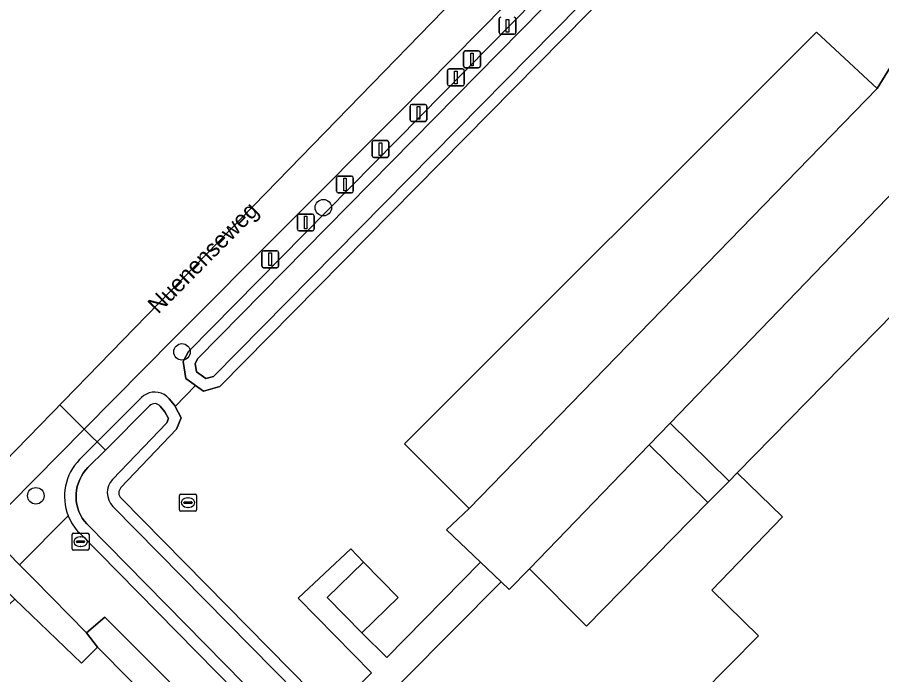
# Model space of a CAD drawing. Extents: x 162788 to 163838, y 385791 to 386523.
# Drawn here: x 162932.6 to 162983.7, y 386211.9 to 386250.8 of the extents above; entities that cross this region are included whole.
import ezdxf

# ---------------------------------------------------------------- set-up
doc = ezdxf.new("R2010")
doc.units = 0
for name, color, linetype in [('IMGEO_Afsluitpaal', 7, 'Continuous'), ('IMGEO_Boom', 7, 'Continuous'), ('IMGEO_Brandkraan', 7, 'Continuous'), ('IMGEO_Duiker', 7, 'Continuous'), ('IMGEO_Erf', 7, 'Continuous'), ('IMGEO_Groenvoorziening', 7, 'Continuous'), ('IMGEO_Oever', 7, 'Continuous'), ('IMGEO_Openbare_ruimte_label', 7, 'Continuous'), ('IMGEO_Pand', 7, 'Continuous'), ('IMGEO_Parkeervlak_halfverhard', 7, 'Continuous'), ('IMGEO_Rijbaan_lokaal_open', 7, 'Continuous'), ('IMGEO_Rioolput', 7, 'Continuous'), ('IMGEO_Voetpad_gesloten', 7, 'Continuous'), ('IMGEO_Voetpad_open', 7, 'Continuous'), ('IMGEO_Waterloop', 7, 'Continuous'), ('IMGEO_Woonerf_open', 7, 'Continuous')]:
    doc.layers.add(name, color=color, linetype=linetype)

msp = doc.modelspace()

# ---------------------------------------------------------------- linework, layer by layer
at = {"layer": 'IMGEO_Afsluitpaal'}
for p, q in [((162961.092, 386249.9), (162961.092, 386250.7)), ((162961.092, 386250.7), (162961.092, 386249.9)), ((162962.082, 386250.7), (162962.082, 386249.9)), ((162962.082, 386249.9), (162962.082, 386250.7)), ((162961.982, 386249.8), (162961.192, 386249.8)), ((162961.192, 386249.8), (162961.982, 386249.8)), ((162958.991, 386247.91), (162958.991, 386248.71)), ((162958.991, 386248.71), (162958.991, 386247.91)), ((162959.091, 386248.81), (162959.881, 386248.81)), ((162959.881, 386248.81), (162959.091, 386248.81)), ((162959.981, 386248.71), (162959.981, 386247.91)), ((162959.981, 386247.91), (162959.981, 386248.71)), ((162958.033, 386246.841), (162958.033, 386247.641)), ((162958.033, 386247.641), (162958.033, 386246.841)), ((162958.133, 386247.741), (162958.923, 386247.741)), ((162958.923, 386247.741), (162958.133, 386247.741)), ((162959.023, 386247.641), (162959.023, 386246.841)), ((162959.023, 386246.841), (162959.023, 386247.641)), ((162959.881, 386247.81), (162959.091, 386247.81)), ((162959.091, 386247.81), (162959.881, 386247.81)), ((162958.923, 386246.741), (162958.133, 386246.741)), ((162958.133, 386246.741), (162958.923, 386246.741)), ((162955.822, 386244.74), (162955.822, 386245.54)), ((162955.822, 386245.54), (162955.822, 386244.74)), ((162955.922, 386245.64), (162956.712, 386245.64)), ((162956.712, 386245.64), (162955.922, 386245.64)), ((162956.812, 386245.54), (162956.812, 386244.74)), ((162956.812, 386244.74), (162956.812, 386245.54)), ((162956.712, 386244.64), (162955.922, 386244.64)), ((162955.922, 386244.64), (162956.712, 386244.64)), ((162953.574, 386242.603), (162953.574, 386243.403)), ((162953.574, 386243.403), (162953.574, 386242.603)), ((162953.674, 386243.503), (162954.464, 386243.503)), ((162954.464, 386243.503), (162953.674, 386243.503)), ((162954.564, 386243.403), (162954.564, 386242.603)), ((162954.564, 386242.603), (162954.564, 386243.403)), ((162954.464, 386242.503), (162953.674, 386242.503)), ((162953.674, 386242.503), (162954.464, 386242.503)), ((162951.473, 386240.502), (162951.473, 386241.302)), ((162951.473, 386241.302), (162951.473, 386240.502)), ((162951.573, 386241.402), (162952.363, 386241.402)), ((162952.363, 386241.402), (162951.573, 386241.402)), ((162952.463, 386241.302), (162952.463, 386240.502)), ((162952.463, 386240.502), (162952.463, 386241.302)), ((162952.363, 386240.402), (162951.573, 386240.402)), ((162951.573, 386240.402), (162952.363, 386240.402)), ((162949.151, 386238.254), (162949.151, 386239.054)), ((162949.151, 386239.054), (162949.151, 386238.254)), ((162949.251, 386239.154), (162950.041, 386239.154)), ((162950.041, 386239.154), (162949.251, 386239.154)), ((162950.141, 386239.054), (162950.141, 386238.254)), ((162950.141, 386238.254), (162950.141, 386239.054)), ((162950.041, 386238.154), (162949.251, 386238.154)), ((162949.251, 386238.154), (162950.041, 386238.154)), ((162947.05, 386236.079), (162947.05, 386236.879)), ((162947.05, 386236.879), (162947.05, 386236.079)), ((162947.15, 386236.979), (162947.94, 386236.979)), ((162947.94, 386236.979), (162947.15, 386236.979)), ((162948.04, 386236.879), (162948.04, 386236.079)), ((162948.04, 386236.079), (162948.04, 386236.879)), ((162947.94, 386235.979), (162947.15, 386235.979)), ((162947.15, 386235.979), (162947.94, 386235.979))]:
    msp.add_line(p, q, dxfattribs=at)
for points in [[(162961.512, 386250.675), (162961.662, 386250.675), (162961.662, 386249.925), (162961.512, 386249.925), (162961.512, 386250.675)], [(162959.411, 386248.685), (162959.561, 386248.685), (162959.561, 386247.935), (162959.411, 386247.935), (162959.411, 386248.685)], [(162958.453, 386247.616), (162958.603, 386247.616), (162958.603, 386246.866), (162958.453, 386246.866), (162958.453, 386247.616)], [(162956.242, 386245.515), (162956.392, 386245.515), (162956.392, 386244.765), (162956.242, 386244.765), (162956.242, 386245.515)], [(162953.994, 386243.378), (162954.144, 386243.378), (162954.144, 386242.628), (162953.994, 386242.628), (162953.994, 386243.378)], [(162951.893, 386241.277), (162952.043, 386241.277), (162952.043, 386240.527), (162951.893, 386240.527), (162951.893, 386241.277)], [(162949.571, 386239.029), (162949.721, 386239.029), (162949.721, 386238.279), (162949.571, 386238.279), (162949.571, 386239.029)], [(162947.47, 386236.854), (162947.62, 386236.854), (162947.62, 386236.104), (162947.47, 386236.104), (162947.47, 386236.854)]]:
    msp.add_lwpolyline(points, dxfattribs=at)
for centre, start, end in [((162961.192, 386250.7), 90, 180), ((162961.192, 386250.7), 90, 180), ((162961.982, 386250.7), 0, 90), ((162961.982, 386250.7), 360, 90), ((162961.192, 386249.9), 180, 270), ((162961.192, 386249.9), 180, 270), ((162961.982, 386249.9), 270, 0), ((162961.982, 386249.9), 270, 0), ((162959.091, 386248.71), 90, 180), ((162959.091, 386248.71), 90, 180), ((162959.881, 386248.71), 0, 90), ((162959.881, 386248.71), 360, 90), ((162959.091, 386247.91), 180, 270), ((162959.091, 386247.91), 180, 270), ((162959.881, 386247.91), 270, 0), ((162959.881, 386247.91), 270, 0), ((162958.133, 386247.641), 90, 180), ((162958.133, 386247.641), 90, 180), ((162958.923, 386247.641), 0, 90), ((162958.923, 386247.641), 360, 90), ((162958.133, 386246.841), 180, 270), ((162958.133, 386246.841), 180, 270), ((162958.923, 386246.841), 270, 0), ((162958.923, 386246.841), 270, 0), ((162955.922, 386245.54), 90, 180), ((162955.922, 386245.54), 90, 180), ((162956.712, 386245.54), 0, 90), ((162956.712, 386245.54), 360, 90), ((162955.922, 386244.74), 180, 270), ((162955.922, 386244.74), 180, 270), ((162956.712, 386244.74), 270, 0), ((162956.712, 386244.74), 270, 0), ((162953.674, 386243.403), 90, 180), ((162953.674, 386243.403), 90, 180), ((162954.464, 386243.403), 0, 90), ((162954.464, 386243.403), 360, 90), ((162953.674, 386242.603), 180, 270), ((162953.674, 386242.603), 180, 270), ((162954.464, 386242.603), 270, 0), ((162954.464, 386242.603), 270, 0), ((162951.573, 386241.302), 90, 180), ((162951.573, 386241.302), 90, 180), ((162952.363, 386241.302), 0, 90), ((162952.363, 386241.302), 360, 90), ((162951.573, 386240.502), 180, 270), ((162951.573, 386240.502), 180, 270), ((162952.363, 386240.502), 270, 0), ((162952.363, 386240.502), 270, 0), ((162949.251, 386239.054), 90, 180), ((162949.251, 386239.054), 90, 180), ((162950.041, 386239.054), 0, 90), ((162950.041, 386239.054), 360, 90), ((162949.251, 386238.254), 180, 270), ((162949.251, 386238.254), 180, 270), ((162950.041, 386238.254), 270, 0), ((162950.041, 386238.254), 270, 0), ((162947.15, 386236.879), 90, 180), ((162947.15, 386236.879), 90, 180), ((162947.94, 386236.879), 0, 90), ((162947.94, 386236.879), 360, 90), ((162947.15, 386236.079), 180, 270), ((162947.15, 386236.079), 180, 270), ((162947.94, 386236.079), 270, 0), ((162947.94, 386236.079), 270, 0)]:
    msp.add_arc(centre, 0.1, start, end, dxfattribs=at)
at = {"layer": 'IMGEO_Boom'}
for centre in [(162950.69, 386239.534), (162942.324, 386230.997), (162933.674, 386222.48)]:
    msp.add_circle(centre, 0.489, dxfattribs=at)
at = {"layer": 'IMGEO_Brandkraan'}
for p, q in [((162935.821, 386219.335), (162935.821, 386220.187)), ((162935.896, 386220.261), (162936.748, 386220.261)), ((162936.123, 386219.804), (162936.521, 386219.804)), ((162936.309, 386220.041), (162936.334, 386220.041)), ((162936.822, 386220.187), (162936.822, 386219.335)), ((162936.748, 386219.261), (162935.896, 386219.261)), ((162936.08, 386219.755), (162936.08, 386219.767)), ((162936.518, 386219.718), (162936.12, 386219.718)), ((162936.332, 386219.481), (162936.307, 386219.481)), ((162936.564, 386219.767), (162936.564, 386219.755))]:
    msp.add_line(p, q, dxfattribs=at)
for points in [[(162935.821, 386219.335), (162935.821, 386220.187)], [(162935.896, 386220.261), (162936.748, 386220.261)], [(162936.822, 386220.187), (162936.822, 386219.335)], [(162936.748, 386219.261), (162935.896, 386219.261)]]:
    msp.add_lwpolyline(points, dxfattribs=at)
for centre, radius, start, end in [((162935.898, 386220.185), 0.0765, 91.552, 178.448), ((162935.898, 386220.185), 0.0765, 91.552, 178.448), ((162936.12, 386219.764), 0.0403, 85.8775, 175.7526), ((162936.525, 386219.766), 0.0386, 1.7309, 96.639), ((162936.746, 386220.185), 0.0765, 1.552, 88.448), ((162936.746, 386220.185), 0.0765, 1.552, 88.448), ((162935.898, 386219.337), 0.0765, 181.552, 268.448), ((162935.898, 386219.337), 0.0765, 181.552, 268.448), ((162936.117, 386219.754), 0.0366, 178.938, 274.7102), ((162936.521, 386219.761), 0.043, 264.8664, 352.4533), ((162936.746, 386219.337), 0.0765, 271.552, 358.448), ((162936.746, 386219.337), 0.0765, 271.552, 358.448)]:
    msp.add_arc(centre, radius, start, end, dxfattribs=at)
for centre, major_axis, ratio, start_param, end_param in [((162936.308, 386219.761), (-0.387, 0.002), 0.722429, 4.712389, 7.853982), ((162936.333, 386219.761), (-0.39, 0.002), 0.717154, 1.570796, 4.712389)]:
    msp.add_ellipse(centre, major_axis=major_axis, ratio=ratio, start_param=start_param, end_param=end_param, dxfattribs=at)
at = {"layer": 'IMGEO_Duiker'}
msp.add_lwpolyline([(162935.089, 386227.868), (162935.089, 386227.868), (162936.539, 386226.429), (162937.792, 386225.185)], dxfattribs=at)
at = {"layer": 'IMGEO_Erf'}
for points in [[(163019.415, 386221.829), (163017.215, 386224.903), (163006.507, 386217.247), (163004.811, 386216.063), (162998.839, 386211.871), (163000, 386210.448), (163000.138, 386210.278), (162990.677, 386200.741), (162991.908, 386199.494), (162983.103, 386190.616), (162967.863, 386205.517), (162976.444, 386214.191), (162973.671, 386216.902), (162977.86, 386221.232), (162975.179, 386223.844)], [(162975.179, 386223.844), (162974.697, 386223.353), (162973.449, 386222.082), (162966.269, 386214.768), (162962.884, 386218.155), (162961.686, 386216.939), (162961.22, 386217.38), (162952.648, 386208.766), (162952.362, 386208.479), (162969.976, 386190.594), (162979.54, 386180.693), (162978.922, 386179.765), (162983.538, 386182.642), (162989.546, 386186.246), (163000.557, 386193.158), (163003.461, 386197.095), (163012.04, 386206.871), (163017.413, 386210.52), (163018.585, 386211.639), (163019.242, 386212.566)], [(162970.367, 386180.135), (162937.328, 386213.523), (162936.374, 386212.581), (162932.44, 386216.361), (162931.108, 386215.134), (162928.515, 386213.329), (162923.893, 386210.577)]]:
    msp.add_lwpolyline(points, dxfattribs=at)
at = {"layer": 'IMGEO_Groenvoorziening'}
for points in [[(163024.046, 386310.479), (163023.535, 386310.538), (163023.359, 386310.538), (163020.272, 386307.421), (163020.444, 386307.251), (163020.549, 386306.986), (163020.601, 386306.514), (163020.576, 386306.01), (163000.486, 386285.642), (162964.856, 386249.521), (162944.555, 386228.94), (162943.594, 386228.666), (162943.128, 386229.005), (162941.921, 386227.771), (162942.281, 386227.087), (162942.005, 386226.417), (162938.714, 386222.971)], [(163020.041, 386309.917), (163018.251, 386309.139), (163000, 386290.614), (162987.698, 386278.128), (162959.944, 386250), (162955.09, 386245.08), (162941.853, 386231.809), (162936.539, 386226.429), (162930.665, 386220.482), (162932.714, 386218.395), (162935.593, 386221.295)], [(162941.557, 386228.226), (162941.883, 386227.843), (162941.921, 386227.771), (162943.128, 386229.005), (162943.049, 386229.062), (162942.55, 386229.422), (162942.399, 386230.424), (162942.706, 386231.014), (162961.879, 386250.479), (162999.514, 386288.687)], [(162938.719, 386222.331), (162951.211, 386209.647), (162952.362, 386208.479), (162952.648, 386208.766), (162951.461, 386209.9), (162953.535, 386211.999), (162949.195, 386216.429), (162952.316, 386219.349), (162953.056, 386218.558), (162955.114, 386216.454), (162952.973, 386214.359), (162954.437, 386212.913), (162959.997, 386218.541), (162957.977, 386220.457), (162959.309, 386221.733), (162955.489, 386225.556), (162979.879, 386249.927), (162983.465, 386246.582), (162984.886, 386248.887), (162987.744, 386256.107), (162989.775, 386258.919), (162997.171, 386269.163)], [(162936.266, 386224.619), (162937.308, 386225.666), (162939.922, 386228.29)], [(162935.593, 386221.295), (162932.714, 386218.395), (162933.575, 386217.518), (162936.664, 386214.373), (162937.755, 386215.292), (162947.333, 386205.72), (162948.52, 386206.922), (162949.688, 386205.791), (162950.095, 386206.2), (162948.953, 386207.361), (162936.252, 386220.279)]]:
    msp.add_lwpolyline(points, dxfattribs=at)
for centre, radius, start, end in [((162940.712, 386227.489), 1.125, 60.8142, 134.5938), ((162940.691, 386227.479), 1.143, 40.7862, 60.1742), ((162938.474, 386222.442), 3.101, 135.4068, 201.7016), ((162939.047, 386222.654), 0.46, 136.3947, 224.5005), ((162938.483, 386222.448), 3.111, 201.7464, 224.1902)]:
    msp.add_arc(centre, radius, start, end, dxfattribs=at)
at = {"layer": 'IMGEO_Oever'}
for points in [[(163020.549, 386306.986), (163020.444, 386307.251), (163020.272, 386307.421), (163019.984, 386307.707), (163019.635, 386307.884), (163019.077, 386308.032), (163018.618, 386308.083), (162999.514, 386288.687), (162961.879, 386250.479), (162942.706, 386231.014), (162942.399, 386230.424), (162942.55, 386229.422), (162943.049, 386229.062), (162943.128, 386229.005), (162943.594, 386228.666), (162944.555, 386228.94), (162964.856, 386249.521), (163000.486, 386285.642), (163020.576, 386306.01), (163020.601, 386306.514)], [(163019.628, 386306.02), (163000, 386286.121), (162964.37, 386250), (162944.195, 386229.547), (162943.726, 386229.413), (162943.449, 386229.614), (162943.182, 386229.807), (162943.107, 386230.306), (162943.264, 386230.608), (162962.365, 386250), (163000, 386288.208), (163018.608, 386307.1), (163019.184, 386306.49)]]:
    msp.add_lwpolyline(points, close=True, dxfattribs=at)
for points in [[(162939.922, 386228.29), (162937.308, 386225.666), (162936.266, 386224.619)], [(162938.714, 386222.971), (162942.005, 386226.417), (162942.281, 386227.087), (162941.921, 386227.771), (162941.883, 386227.843), (162941.557, 386228.226)], [(162977.188, 386179.619), (162936.744, 386220.751), (162936.686, 386220.813), (162936.548, 386220.979), (162936.425, 386221.157), (162936.318, 386221.346), (162936.229, 386221.543), (162936.158, 386221.747), (162936.105, 386221.957), (162936.071, 386222.171), (162936.057, 386222.387), (162936.061, 386222.603), (162936.086, 386222.818), (162936.129, 386223.03), (162936.191, 386223.238), (162936.271, 386223.439), (162936.369, 386223.632), (162936.484, 386223.815), (162936.614, 386223.988), (162936.76, 386224.148), (162937.792, 386225.185), (162940.405, 386227.808)], [(162941.038, 386227.783), (162941.315, 386227.458), (162941.529, 386227.052), (162941.423, 386226.795), (162938.221, 386223.442)], [(162952.362, 386208.479), (162951.211, 386209.647), (162938.719, 386222.331)], [(162938.232, 386221.853), (162969.488, 386190.118)], [(162936.252, 386220.279), (162948.953, 386207.361), (162950.095, 386206.2), (162976.888, 386178.951), (162977.561, 386178.917), (162978.922, 386179.765), (162979.54, 386180.693), (162969.976, 386190.594), (162952.362, 386208.479)]]:
    msp.add_lwpolyline(points, dxfattribs=at)
for centre, radius, start, end in [((162940.712, 386227.489), 1.125, 60.8142, 134.5938), ((162940.691, 386227.479), 1.143, 40.7862, 60.1742), ((162940.71, 386227.503), 0.431, 40.4697, 135.0069), ((162938.474, 386222.442), 3.101, 135.4068, 201.7016), ((162939.047, 386222.653), 1.142, 136.3343, 224.459), ((162939.047, 386222.654), 0.46, 136.3947, 224.5005), ((162938.483, 386222.448), 3.111, 201.7464, 224.1902)]:
    msp.add_arc(centre, radius, start, end, dxfattribs=at)
at = {"layer": 'IMGEO_Pand'}
for points in [[(163004.708, 386220.778), (163012.988, 386226.739), (163001.488, 386242.784), (162990.889, 386235.198), (162988.569, 386237.483), (162975.179, 386223.844), (162977.86, 386221.232), (162973.671, 386216.902), (162976.444, 386214.191), (162967.863, 386205.517), (162983.103, 386190.616), (162991.908, 386199.494), (162990.677, 386200.741), (163000.138, 386210.278), (163000, 386210.448), (162998.839, 386211.871), (163004.811, 386216.063), (163002.528, 386219.208), (163004.161, 386220.384)], [(162955.114, 386216.454), (162953.056, 386218.558), (162950.915, 386216.463), (162952.973, 386214.359)]]:
    msp.add_lwpolyline(points, close=True, dxfattribs=at)
at = {"layer": 'IMGEO_Parkeervlak_halfverhard'}
for points in [[(162983.465, 386246.582), (162979.879, 386249.927), (162955.489, 386225.556), (162959.309, 386221.733)], [(162988.569, 386237.483), (162995.78, 386244.695), (162992.066, 386248.409), (162971.204, 386226.781), (162974.697, 386223.353), (162975.179, 386223.844)], [(162973.449, 386222.082), (162969.968, 386225.5), (162962.884, 386218.155), (162966.269, 386214.768)]]:
    msp.add_lwpolyline(points, close=True, dxfattribs=at)
at = {"layer": 'IMGEO_Rijbaan_lokaal_open'}
msp.add_lwpolyline([(163145.974, 386442.657), (162994.999, 386289.478), (162926.188, 386218.715), (162917.231, 386215.618), (162918.642, 386212.196), (162921.179, 386213.365), (162927.186, 386216.882), (162929.139, 386218.937), (162929.526, 386219.329), (162930.665, 386220.482), (162936.539, 386226.429), (162941.853, 386231.809), (162955.09, 386245.08), (162959.944, 386250), (162987.698, 386278.128), (163000, 386290.614), (163018.251, 386309.139), (163024.508, 386315.489), (163032.796, 386323.924)], dxfattribs=at)
at = {"layer": 'IMGEO_Rioolput'}
for p, q in [((162942.177, 386221.649), (162942.177, 386222.501)), ((162942.252, 386222.575), (162943.104, 386222.575)), ((162942.665, 386222.355), (162942.69, 386222.355)), ((162943.178, 386222.501), (162943.178, 386221.649)), ((162942.436, 386222.069), (162942.436, 386222.081)), ((162942.874, 386222.032), (162942.476, 386222.032)), ((162942.479, 386222.118), (162942.877, 386222.118)), ((162942.92, 386222.081), (162942.92, 386222.069)), ((162943.104, 386221.575), (162942.252, 386221.575)), ((162942.688, 386221.795), (162942.663, 386221.795))]:
    msp.add_line(p, q, dxfattribs=at)
for points in [[(162942.177, 386221.649), (162942.177, 386222.501)], [(162942.252, 386222.575), (162943.104, 386222.575)], [(162943.178, 386222.501), (162943.178, 386221.649)], [(162943.104, 386221.575), (162942.252, 386221.575)]]:
    msp.add_lwpolyline(points, dxfattribs=at)
for centre, radius, start, end in [((162942.254, 386222.499), 0.0765, 91.552, 178.448), ((162942.254, 386222.499), 0.0765, 91.552, 178.448), ((162943.102, 386222.499), 0.0765, 1.552, 88.448), ((162943.102, 386222.499), 0.0765, 1.552, 88.448), ((162942.476, 386222.078), 0.0403, 85.8775, 175.7526), ((162942.473, 386222.068), 0.0366, 178.938, 274.7102), ((162942.877, 386222.075), 0.043, 264.8664, 352.4533), ((162942.881, 386222.08), 0.0386, 1.7309, 96.639), ((162942.254, 386221.651), 0.0765, 181.552, 268.448), ((162942.254, 386221.651), 0.0765, 181.552, 268.448), ((162943.102, 386221.651), 0.0765, 271.552, 358.448), ((162943.102, 386221.651), 0.0765, 271.552, 358.448)]:
    msp.add_arc(centre, radius, start, end, dxfattribs=at)
for centre, major_axis, ratio, start_param, end_param in [((162942.664, 386222.075), (-0.387, 0.002), 0.722429, 4.712389, 7.853982), ((162942.689, 386222.075), (-0.39, 0.002), 0.717154, 1.570796, 4.712389)]:
    msp.add_ellipse(centre, major_axis=major_axis, ratio=ratio, start_param=start_param, end_param=end_param, dxfattribs=at)
at = {"layer": 'IMGEO_Voetpad_gesloten'}
msp.add_lwpolyline([(162933.575, 386217.518), (162932.714, 386218.395), (162930.665, 386220.482), (162929.526, 386219.329), (162931.15, 386217.665), (162932.44, 386216.361), (162936.374, 386212.581), (162937.328, 386213.523), (162936.664, 386214.373)], close=True, dxfattribs=at)
at = {"layer": 'IMGEO_Voetpad_open'}
for points in [[(162974.697, 386223.353), (162971.204, 386226.781), (162969.968, 386225.5), (162973.449, 386222.082)], [(162961.22, 386217.38), (162959.997, 386218.541), (162954.437, 386212.913), (162952.973, 386214.359), (162950.915, 386216.463), (162953.056, 386218.558), (162952.316, 386219.349), (162949.195, 386216.429), (162953.535, 386211.999), (162951.461, 386209.9), (162952.648, 386208.766)]]:
    msp.add_lwpolyline(points, close=True, dxfattribs=at)
at = {"layer": 'IMGEO_Waterloop'}
msp.add_lwpolyline([(162943.449, 386229.614), (162943.726, 386229.413), (162944.195, 386229.547), (162964.37, 386250), (163000, 386286.121), (163019.628, 386306.02), (163019.184, 386306.49), (163018.608, 386307.1), (163000, 386288.208), (162962.365, 386250), (162943.264, 386230.608), (162943.107, 386230.306), (162943.182, 386229.807)], close=True, dxfattribs=at)
for points in [[(162940.405, 386227.808), (162937.792, 386225.185), (162936.76, 386224.148), (162936.614, 386223.988), (162936.484, 386223.815), (162936.369, 386223.632), (162936.271, 386223.439), (162936.191, 386223.238), (162936.129, 386223.03), (162936.086, 386222.818), (162936.061, 386222.603), (162936.057, 386222.387), (162936.071, 386222.171), (162936.105, 386221.957), (162936.158, 386221.747), (162936.229, 386221.543), (162936.318, 386221.346), (162936.425, 386221.157), (162936.548, 386220.979), (162936.686, 386220.813), (162936.744, 386220.751), (162977.188, 386179.619)], [(162938.221, 386223.442), (162941.423, 386226.795), (162941.529, 386227.052), (162941.315, 386227.458), (162941.038, 386227.783)], [(162969.488, 386190.118), (162938.232, 386221.853)]]:
    msp.add_lwpolyline(points, dxfattribs=at)
for centre, radius, start, end in [((162940.71, 386227.503), 0.431, 40.4697, 135.0069), ((162939.047, 386222.653), 1.142, 136.3343, 224.459)]:
    msp.add_arc(centre, radius, start, end, dxfattribs=at)
at = {"layer": 'IMGEO_Woonerf_open'}
for points in [[(162997.171, 386269.163), (162989.775, 386258.919), (162987.744, 386256.107), (162984.886, 386248.887), (162983.465, 386246.582), (162959.309, 386221.733), (162957.977, 386220.457), (162959.997, 386218.541), (162961.22, 386217.38), (162961.686, 386216.939), (162962.884, 386218.155), (162969.968, 386225.5), (162971.204, 386226.781), (162992.066, 386248.409)], [(162947.333, 386205.72), (162937.755, 386215.292), (162936.664, 386214.373), (162937.328, 386213.523), (162970.367, 386180.135)]]:
    msp.add_lwpolyline(points, dxfattribs=at)

# ---------------------------------------------------------------- texts
at = {"layer": 'IMGEO_Openbare_ruimte_label'}
msp.add_text('Nuenenseweg', height=1, rotation=45.3242, dxfattribs=at).set_placement((162940.914, 386233.195))

doc.saveas('drawing.dxf')
